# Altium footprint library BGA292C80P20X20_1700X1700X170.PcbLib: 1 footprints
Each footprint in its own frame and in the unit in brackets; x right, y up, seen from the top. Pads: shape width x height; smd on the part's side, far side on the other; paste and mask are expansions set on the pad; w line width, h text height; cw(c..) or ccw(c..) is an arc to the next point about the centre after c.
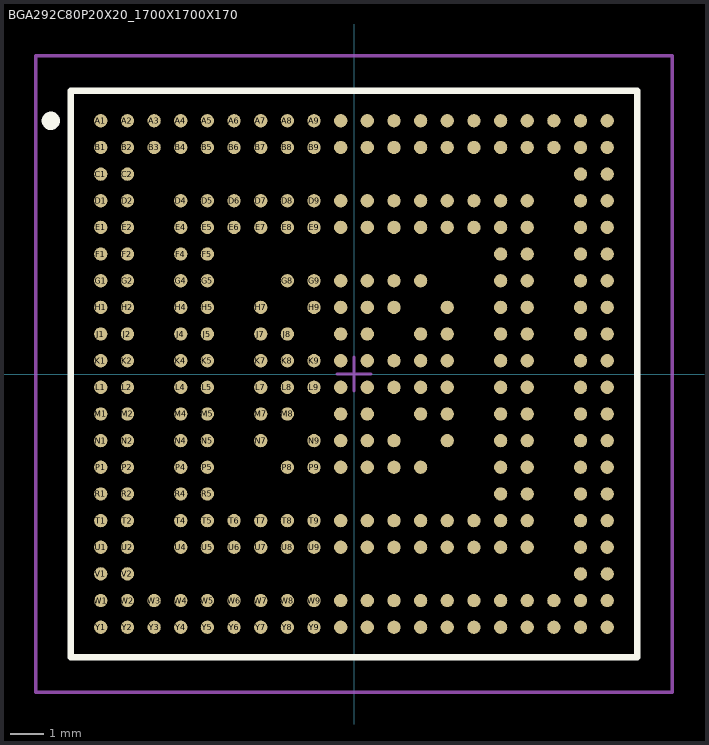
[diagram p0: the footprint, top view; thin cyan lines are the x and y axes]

## BGA292C80P20X20_1700X1700X170 [mm] "BGA,0.80mm pitch,square;292 pin,20 columns X 20 rows,17.00mm X 17.00mm X 1.70mm H"
height 1.7
pads (292):
  round 0.4 smd paste+0 mask+0: A1(-7.6,7.6) A2(-6.8,7.6) A3(-6,7.6) A4(-5.2,7.6) A5(-4.4,7.6) A6(-3.6,7.6) A7(-2.8,7.6) A8(-2,7.6) A9(-1.2,7.6) A10(-0.4,7.6) A11(0.4,7.6) A12(1.2,7.6) A13(2,7.6) A14(2.8,7.6) A15(3.6,7.6) A16(4.4,7.6) A17(5.2,7.6) A18(6,7.6) A19(6.8,7.6) A20(7.6,7.6) B1(-7.6,6.8) B2(-6.8,6.8) B3(-6,6.8) B4(-5.2,6.8) B5(-4.4,6.8) B6(-3.6,6.8) B7(-2.8,6.8) B8(-2,6.8) B9(-1.2,6.8) B10(-0.4,6.8) B11(0.4,6.8) B12(1.2,6.8) B13(2,6.8) B14(2.8,6.8) B15(3.6,6.8) B16(4.4,6.8) B17(5.2,6.8) B18(6,6.8) B19(6.8,6.8) B20(7.6,6.8) C1(-7.6,6) C2(-6.8,6) C19(6.8,6) C20(7.6,6) D1(-7.6,5.2) D2(-6.8,5.2) D4(-5.2,5.2) D5(-4.4,5.2) D6(-3.6,5.2) D7(-2.8,5.2) D8(-2,5.2) D9(-1.2,5.2) D10(-0.4,5.2) D11(0.4,5.2) D12(1.2,5.2) D13(2,5.2) D14(2.8,5.2) D15(3.6,5.2) D16(4.4,5.2) D17(5.2,5.2) D19(6.8,5.2) D20(7.6,5.2) E1(-7.6,4.4) E2(-6.8,4.4) E4(-5.2,4.4) E5(-4.4,4.4) E6(-3.6,4.4) E7(-2.8,4.4) E8(-2,4.4) E9(-1.2,4.4) E10(-0.4,4.4) E11(0.4,4.4) E12(1.2,4.4) E13(2,4.4) E14(2.8,4.4) E15(3.6,4.4) E16(4.4,4.4) E17(5.2,4.4) E19(6.8,4.4) E20(7.6,4.4) F1(-7.6,3.6) F2(-6.8,3.6) F4(-5.2,3.6) F5(-4.4,3.6) F16(4.4,3.6) F17(5.2,3.6) F19(6.8,3.6) F20(7.6,3.6) G1(-7.6,2.8) G2(-6.8,2.8) G4(-5.2,2.8) G5(-4.4,2.8) G8(-2,2.8) G9(-1.2,2.8) G10(-0.4,2.8) G11(0.4,2.8) G12(1.2,2.8) G13(2,2.8) G16(4.4,2.8) G17(5.2,2.8) G19(6.8,2.8) G20(7.6,2.8) H1(-7.6,2) H2(-6.8,2) H4(-5.2,2) H5(-4.4,2) H7(-2.8,2) H9(-1.2,2) H10(-0.4,2) H11(0.4,2) H12(1.2,2) H14(2.8,2) H16(4.4,2) H17(5.2,2) H19(6.8,2) H20(7.6,2) J1(-7.6,1.2) J2(-6.8,1.2) J4(-5.2,1.2) J5(-4.4,1.2) J7(-2.8,1.2) J8(-2,1.2) J10(-0.4,1.2) J11(0.4,1.2) J13(2,1.2) J14(2.8,1.2) J16(4.4,1.2) J17(5.2,1.2) J19(6.8,1.2) J20(7.6,1.2) K1(-7.6,0.4) K2(-6.8,0.4) K4(-5.2,0.4) K5(-4.4,0.4) K7(-2.8,0.4) K8(-2,0.4) K9(-1.2,0.4) K10(-0.4,0.4) K11(0.4,0.4) K12(1.2,0.4) K13(2,0.4) K14(2.8,0.4) K16(4.4,0.4) K17(5.2,0.4) K19(6.8,0.4) K20(7.6,0.4) L1(-7.6,-0.4) L2(-6.8,-0.4) L4(-5.2,-0.4) L5(-4.4,-0.4) L7(-2.8,-0.4) L8(-2,-0.4) L9(-1.2,-0.4) L10(-0.4,-0.4) L11(0.4,-0.4) L12(1.2,-0.4) L13(2,-0.4) L14(2.8,-0.4) L16(4.4,-0.4) L17(5.2,-0.4) L19(6.8,-0.4) L20(7.6,-0.4) M1(-7.6,-1.2) M2(-6.8,-1.2) M4(-5.2,-1.2) M5(-4.4,-1.2) M7(-2.8,-1.2) M8(-2,-1.2) M10(-0.4,-1.2) M11(0.4,-1.2) M13(2,-1.2) M14(2.8,-1.2) M16(4.4,-1.2) M17(5.2,-1.2) M19(6.8,-1.2) M20(7.6,-1.2) N1(-7.6,-2) N2(-6.8,-2) N4(-5.2,-2) N5(-4.4,-2) N7(-2.8,-2) N9(-1.2,-2) N10(-0.4,-2) N11(0.4,-2) N12(1.2,-2) N14(2.8,-2) N16(4.4,-2) N17(5.2,-2) N19(6.8,-2) N20(7.6,-2) P1(-7.6,-2.8) P2(-6.8,-2.8) P4(-5.2,-2.8) P5(-4.4,-2.8) P8(-2,-2.8) P9(-1.2,-2.8) P10(-0.4,-2.8) P11(0.4,-2.8) P12(1.2,-2.8) P13(2,-2.8) P16(4.4,-2.8) P17(5.2,-2.8) P19(6.8,-2.8) P20(7.6,-2.8) R1(-7.6,-3.6) R2(-6.8,-3.6) R4(-5.2,-3.6) R5(-4.4,-3.6) R16(4.4,-3.6) R17(5.2,-3.6) R19(6.8,-3.6) R20(7.6,-3.6) T1(-7.6,-4.4) T2(-6.8,-4.4) T4(-5.2,-4.4) T5(-4.4,-4.4) T6(-3.6,-4.4) T7(-2.8,-4.4) T8(-2,-4.4) T9(-1.2,-4.4) T10(-0.4,-4.4) T11(0.4,-4.4) T12(1.2,-4.4) T13(2,-4.4) T14(2.8,-4.4) T15(3.6,-4.4) T16(4.4,-4.4) T17(5.2,-4.4) T19(6.8,-4.4) T20(7.6,-4.4) U1(-7.6,-5.2) U2(-6.8,-5.2) U4(-5.2,-5.2) U5(-4.4,-5.2) U6(-3.6,-5.2) U7(-2.8,-5.2) U8(-2,-5.2) U9(-1.2,-5.2) U10(-0.4,-5.2) U11(0.4,-5.2) U12(1.2,-5.2) U13(2,-5.2) U14(2.8,-5.2) U15(3.6,-5.2) U16(4.4,-5.2) U17(5.2,-5.2) U19(6.8,-5.2) U20(7.6,-5.2) V1(-7.6,-6) V2(-6.8,-6) V19(6.8,-6) V20(7.6,-6) W1(-7.6,-6.8) W2(-6.8,-6.8) W3(-6,-6.8) W4(-5.2,-6.8) W5(-4.4,-6.8) W6(-3.6,-6.8) W7(-2.8,-6.8) W8(-2,-6.8) W9(-1.2,-6.8) W10(-0.4,-6.8) W11(0.4,-6.8) W12(1.2,-6.8) W13(2,-6.8) W14(2.8,-6.8) W15(3.6,-6.8) W16(4.4,-6.8) W17(5.2,-6.8) W18(6,-6.8) W19(6.8,-6.8) W20(7.6,-6.8) Y1(-7.6,-7.6) Y2(-6.8,-7.6) Y3(-6,-7.6) Y4(-5.2,-7.6) Y5(-4.4,-7.6) Y6(-3.6,-7.6) Y7(-2.8,-7.6) Y8(-2,-7.6) Y9(-1.2,-7.6) Y10(-0.4,-7.6) Y11(0.4,-7.6) Y12(1.2,-7.6) Y13(2,-7.6) Y14(2.8,-7.6) Y15(3.6,-7.6) Y16(4.4,-7.6) Y17(5.2,-7.6) Y18(6,-7.6) Y19(6.8,-7.6) Y20(7.6,-7.6)
Top Overlay:
  circle w0.3: c-9.1,7.6 r0.125
  lines w0.2: -8.5,-8.5 -8.5,8.5 8.5,8.5 8.5,-8.5 -8.5,-8.5
M3 (ASY_Text_Top):
  text ".DESIGNATOR" at 0,0 h1.2
M13 (CMP_Body_OTL_Top):
  lines w0.1: -8.5,-8.5 -8.5,8.5 8.5,8.5 8.5,-8.5 -8.5,-8.5
M15 (CMP_Courtyard_Top):
  lines w0.1: -0.5,0 0.5,0 ; 0,-0.5 0,0.5 ; -9.55,-9.55 -9.55,9.55 9.55,9.55 9.55,-9.55 -9.55,-9.55
3D body: height 0.45, standoff -0.05, extent -7.847,7.351 -7.35,7.849
3D body: height 1.71, standoff 1.7, extent -7.92,7.28 -7.32,7.879
3D body: height 0.45, standoff -0.05, extent -7.847,6.551 -7.35,7.049
3D body: height 0.45, standoff -0.05, extent -7.047,6.551 -6.55,7.049
3D body: height 0.45, standoff -0.05, extent -7.047,7.351 -6.55,7.849
3D body: height 0.45, standoff -0.05, extent -6.247,7.351 -5.75,7.849
3D body: height 0.45, standoff -0.05, extent -6.247,6.551 -5.75,7.049
3D body: height 0.45, standoff -0.05, extent -5.447,7.351 -4.95,7.849
3D body: height 0.45, standoff -0.05, extent -5.447,6.551 -4.95,7.049
3D body: height 0.45, standoff -0.05, extent -4.647,7.351 -4.15,7.849
3D body: height 0.45, standoff -0.05, extent -4.647,6.551 -4.15,7.049
3D body: height 0.45, standoff -0.05, extent -3.847,7.351 -3.35,7.849
3D body: height 0.45, standoff -0.05, extent -3.847,6.551 -3.35,7.049
3D body: height 0.45, standoff -0.05, extent -3.047,7.351 -2.55,7.849
3D body: height 0.45, standoff -0.05, extent -3.047,6.551 -2.55,7.049
3D body: height 0.45, standoff -0.05, extent -2.247,7.351 -1.75,7.849
3D body: height 0.45, standoff -0.05, extent -2.247,6.551 -1.75,7.049
3D body: height 0.45, standoff -0.05, extent -1.447,7.351 -0.95,7.849
3D body: height 0.45, standoff -0.05, extent -1.447,6.551 -0.95,7.049
3D body: height 0.45, standoff -0.05, extent -0.647,7.351 -0.15,7.849
3D body: height 0.45, standoff -0.05, extent -0.647,6.551 -0.15,7.049
3D body: height 0.45, standoff -0.05, extent 0.153,7.351 0.65,7.849
3D body: height 0.45, standoff -0.05, extent 0.153,6.551 0.65,7.049
3D body: height 0.45, standoff -0.05, extent 0.953,7.351 1.45,7.849
3D body: height 0.45, standoff -0.05, extent 0.953,6.551 1.45,7.049
3D body: height 0.45, standoff -0.05, extent 1.753,7.351 2.25,7.849
3D body: height 0.45, standoff -0.05, extent 1.753,6.551 2.25,7.049
3D body: height 0.45, standoff -0.05, extent 2.553,7.351 3.05,7.849
3D body: height 0.45, standoff -0.05, extent 2.553,6.551 3.05,7.049
3D body: height 0.45, standoff -0.05, extent 3.353,7.351 3.85,7.849
3D body: height 0.45, standoff -0.05, extent 3.353,6.551 3.85,7.049
3D body: height 0.45, standoff -0.05, extent 4.153,7.351 4.65,7.849
3D body: height 0.45, standoff -0.05, extent 4.153,6.551 4.65,7.049
3D body: height 0.45, standoff -0.05, extent 4.953,7.351 5.45,7.849
3D body: height 0.45, standoff -0.05, extent 4.953,6.551 5.45,7.049
3D body: height 0.45, standoff -0.05, extent 5.753,7.351 6.25,7.849
3D body: height 0.45, standoff -0.05, extent 5.753,6.551 6.25,7.049
3D body: height 0.45, standoff -0.05, extent 6.553,7.351 7.05,7.849
3D body: height 0.45, standoff -0.05, extent 6.553,6.551 7.05,7.049
3D body: height 0.45, standoff -0.05, extent 7.353,7.351 7.85,7.849
3D body: height 0.45, standoff -0.05, extent 7.353,6.551 7.85,7.049
3D body: height 0.45, standoff -0.05, extent 6.553,5.751 7.05,6.249
3D body: height 0.45, standoff -0.05, extent 6.553,4.951 7.05,5.449
3D body: height 0.45, standoff -0.05, extent 6.553,4.151 7.05,4.649
3D body: height 0.45, standoff -0.05, extent 6.553,3.351 7.05,3.849
3D body: height 0.45, standoff -0.05, extent 6.553,2.551 7.05,3.049
3D body: height 0.45, standoff -0.05, extent 6.553,1.751 7.05,2.249
3D body: height 0.45, standoff -0.05, extent 6.553,0.951 7.05,1.449
3D body: height 0.45, standoff -0.05, extent 6.553,0.151 7.05,0.649
3D body: height 0.45, standoff -0.05, extent 6.553,-0.649 7.05,-0.151
3D body: height 0.45, standoff -0.05, extent 6.553,-1.449 7.05,-0.951
3D body: height 0.45, standoff -0.05, extent 6.553,-2.249 7.05,-1.751
3D body: height 0.45, standoff -0.05, extent 6.553,-3.049 7.05,-2.551
3D body: height 0.45, standoff -0.05, extent 6.553,-3.849 7.05,-3.351
3D body: height 0.45, standoff -0.05, extent 6.553,-4.649 7.05,-4.151
3D body: height 0.45, standoff -0.05, extent 6.553,-5.449 7.05,-4.951
3D body: height 0.45, standoff -0.05, extent 6.553,-6.249 7.05,-5.751
3D body: height 0.45, standoff -0.05, extent 6.553,-7.049 7.05,-6.551
3D body: height 0.45, standoff -0.05, extent 6.553,-7.849 7.05,-7.351
3D body: height 0.45, standoff -0.05, extent 7.353,-7.849 7.85,-7.351
3D body: height 0.45, standoff -0.05, extent 7.353,-7.049 7.85,-6.551
3D body: height 0.45, standoff -0.05, extent 7.353,-6.249 7.85,-5.751
3D body: height 0.45, standoff -0.05, extent 7.353,-5.449 7.85,-4.951
3D body: height 0.45, standoff -0.05, extent 7.353,-4.649 7.85,-4.151
3D body: height 0.45, standoff -0.05, extent 7.353,-3.849 7.85,-3.351
3D body: height 0.45, standoff -0.05, extent 7.353,-3.049 7.85,-2.551
3D body: height 0.45, standoff -0.05, extent 7.353,-2.249 7.85,-1.751
3D body: height 0.45, standoff -0.05, extent 7.353,-1.449 7.85,-0.951
3D body: height 0.45, standoff -0.05, extent 7.353,-0.649 7.85,-0.151
3D body: height 0.45, standoff -0.05, extent 7.353,0.151 7.85,0.649
3D body: height 0.45, standoff -0.05, extent 7.353,0.951 7.85,1.449
3D body: height 0.45, standoff -0.05, extent 7.353,1.751 7.85,2.249
3D body: height 0.45, standoff -0.05, extent 7.353,2.551 7.85,3.049
3D body: height 0.45, standoff -0.05, extent 7.353,3.351 7.85,3.849
3D body: height 0.45, standoff -0.05, extent 7.353,4.151 7.85,4.649
3D body: height 0.45, standoff -0.05, extent 7.353,4.951 7.85,5.449
3D body: height 0.45, standoff -0.05, extent 7.353,5.751 7.85,6.249
3D body: height 0.45, standoff -0.05, extent -7.847,-7.049 -7.35,-6.551
3D body: height 0.45, standoff -0.05, extent -7.847,-7.849 -7.35,-7.351
3D body: height 0.45, standoff -0.05, extent -7.047,-7.049 -6.55,-6.551
3D body: height 0.45, standoff -0.05, extent -7.047,-7.849 -6.55,-7.351
3D body: height 0.45, standoff -0.05, extent -6.247,-7.049 -5.75,-6.551
3D body: height 0.45, standoff -0.05, extent -6.247,-7.849 -5.75,-7.351
3D body: height 0.45, standoff -0.05, extent -5.447,-7.049 -4.95,-6.551
3D body: height 0.45, standoff -0.05, extent -5.447,-7.849 -4.95,-7.351
3D body: height 0.45, standoff -0.05, extent -4.647,-7.049 -4.15,-6.551
3D body: height 0.45, standoff -0.05, extent -4.647,-7.849 -4.15,-7.351
3D body: height 0.45, standoff -0.05, extent -3.847,-7.049 -3.35,-6.551
3D body: height 0.45, standoff -0.05, extent -3.847,-7.849 -3.35,-7.351
3D body: height 0.45, standoff -0.05, extent -3.047,-7.049 -2.55,-6.551
3D body: height 0.45, standoff -0.05, extent -3.047,-7.849 -2.55,-7.351
3D body: height 0.45, standoff -0.05, extent -2.247,-7.049 -1.75,-6.551
3D body: height 0.45, standoff -0.05, extent -2.247,-7.849 -1.75,-7.351
3D body: height 0.45, standoff -0.05, extent -1.447,-7.049 -0.95,-6.551
3D body: height 0.45, standoff -0.05, extent -1.447,-7.849 -0.95,-7.351
3D body: height 0.45, standoff -0.05, extent -0.647,-7.049 -0.15,-6.551
3D body: height 0.45, standoff -0.05, extent -0.647,-7.849 -0.15,-7.351
3D body: height 0.45, standoff -0.05, extent 0.153,-7.049 0.65,-6.551
3D body: height 0.45, standoff -0.05, extent 0.153,-7.849 0.65,-7.351
3D body: height 0.45, standoff -0.05, extent 0.953,-7.049 1.45,-6.551
3D body: height 0.45, standoff -0.05, extent 0.953,-7.849 1.45,-7.351
3D body: height 0.45, standoff -0.05, extent 1.753,-7.049 2.25,-6.551
3D body: height 0.45, standoff -0.05, extent 1.753,-7.849 2.25,-7.351
3D body: height 0.45, standoff -0.05, extent 2.553,-7.049 3.05,-6.551
3D body: height 0.45, standoff -0.05, extent 2.553,-7.849 3.05,-7.351
3D body: height 0.45, standoff -0.05, extent 3.353,-7.049 3.85,-6.551
3D body: height 0.45, standoff -0.05, extent 3.353,-7.849 3.85,-7.351
3D body: height 0.45, standoff -0.05, extent 4.153,-7.049 4.65,-6.551
3D body: height 0.45, standoff -0.05, extent 4.153,-7.849 4.65,-7.351
3D body: height 0.45, standoff -0.05, extent 4.953,-7.049 5.45,-6.551
3D body: height 0.45, standoff -0.05, extent 4.953,-7.849 5.45,-7.351
3D body: height 0.45, standoff -0.05, extent 5.753,-7.049 6.25,-6.551
3D body: height 0.45, standoff -0.05, extent 5.753,-7.849 6.25,-7.351
3D body: height 0.45, standoff -0.05, extent -7.847,5.751 -7.35,6.249
3D body: height 0.45, standoff -0.05, extent -7.847,4.951 -7.35,5.449
3D body: height 0.45, standoff -0.05, extent -7.847,4.151 -7.35,4.649
3D body: height 0.45, standoff -0.05, extent -7.847,3.351 -7.35,3.849
3D body: height 0.45, standoff -0.05, extent -7.847,2.551 -7.35,3.049
3D body: height 0.45, standoff -0.05, extent -7.847,1.751 -7.35,2.249
3D body: height 0.45, standoff -0.05, extent -7.847,0.951 -7.35,1.449
3D body: height 0.45, standoff -0.05, extent -7.847,0.151 -7.35,0.649
3D body: height 0.45, standoff -0.05, extent -7.847,-0.649 -7.35,-0.151
3D body: height 0.45, standoff -0.05, extent -7.847,-1.449 -7.35,-0.951
3D body: height 0.45, standoff -0.05, extent -7.847,-2.249 -7.35,-1.751
3D body: height 0.45, standoff -0.05, extent -7.847,-3.049 -7.35,-2.551
3D body: height 0.45, standoff -0.05, extent -7.847,-3.849 -7.35,-3.351
3D body: height 0.45, standoff -0.05, extent -7.847,-4.649 -7.35,-4.151
3D body: height 0.45, standoff -0.05, extent -7.847,-5.449 -7.35,-4.951
3D body: height 0.45, standoff -0.05, extent -7.047,-5.449 -6.55,-4.951
3D body: height 0.45, standoff -0.05, extent -7.047,-4.649 -6.55,-4.151
3D body: height 0.45, standoff -0.05, extent -7.047,-3.849 -6.55,-3.351
3D body: height 0.45, standoff -0.05, extent -7.047,-3.049 -6.55,-2.551
3D body: height 0.45, standoff -0.05, extent -7.047,-2.249 -6.55,-1.751
3D body: height 0.45, standoff -0.05, extent -7.047,-1.449 -6.55,-0.951
3D body: height 0.45, standoff -0.05, extent -7.047,-0.649 -6.55,-0.151
3D body: height 0.45, standoff -0.05, extent -7.047,0.151 -6.55,0.649
3D body: height 0.45, standoff -0.05, extent -7.047,0.951 -6.55,1.449
3D body: height 0.45, standoff -0.05, extent -7.047,1.751 -6.55,2.249
3D body: height 0.45, standoff -0.05, extent -7.047,2.551 -6.55,3.049
3D body: height 0.45, standoff -0.05, extent -7.047,3.351 -6.55,3.849
3D body: height 0.45, standoff -0.05, extent -7.047,4.151 -6.55,4.649
3D body: height 0.45, standoff -0.05, extent -7.047,4.951 -6.55,5.449
3D body: height 0.45, standoff -0.05, extent -7.047,5.751 -6.55,6.249
3D body: height 0.45, standoff -0.05, extent -5.447,4.951 -4.95,5.449
3D body: height 0.45, standoff -0.05, extent -5.447,4.151 -4.95,4.649
3D body: height 0.45, standoff -0.05, extent -5.447,3.351 -4.95,3.849
3D body: height 0.45, standoff -0.05, extent -5.447,2.551 -4.95,3.049
3D body: height 0.45, standoff -0.05, extent -5.447,1.751 -4.95,2.249
3D body: height 0.45, standoff -0.05, extent -5.447,0.951 -4.95,1.449
3D body: height 0.45, standoff -0.05, extent -5.447,0.151 -4.95,0.649
3D body: height 0.45, standoff -0.05, extent -5.447,-0.649 -4.95,-0.151
3D body: height 0.45, standoff -0.05, extent -5.447,-1.449 -4.95,-0.951
3D body: height 0.45, standoff -0.05, extent -5.447,-2.249 -4.95,-1.751
3D body: height 0.45, standoff -0.05, extent -5.447,-3.049 -4.95,-2.551
3D body: height 0.45, standoff -0.05, extent -5.447,-3.849 -4.95,-3.351
3D body: height 0.45, standoff -0.05, extent -5.447,-4.649 -4.95,-4.151
3D body: height 0.45, standoff -0.05, extent -5.447,-5.449 -4.95,-4.951
3D body: height 0.45, standoff -0.05, extent -4.647,-5.449 -4.15,-4.951
3D body: height 0.45, standoff -0.05, extent -4.647,-4.649 -4.15,-4.151
3D body: height 0.45, standoff -0.05, extent -4.647,-3.849 -4.15,-3.351
3D body: height 0.45, standoff -0.05, extent -4.647,-3.049 -4.15,-2.551
3D body: height 0.45, standoff -0.05, extent -4.647,-2.249 -4.15,-1.751
3D body: height 0.45, standoff -0.05, extent -4.647,-1.449 -4.15,-0.951
3D body: height 0.45, standoff -0.05, extent -4.647,-0.649 -4.15,-0.151
3D body: height 0.45, standoff -0.05, extent -4.647,0.151 -4.15,0.649
3D body: height 0.45, standoff -0.05, extent -4.647,0.951 -4.15,1.449
3D body: height 0.45, standoff -0.05, extent -4.647,1.751 -4.15,2.249
3D body: height 0.45, standoff -0.05, extent -4.647,2.551 -4.15,3.049
3D body: height 0.45, standoff -0.05, extent -4.647,3.351 -4.15,3.849
3D body: height 0.45, standoff -0.05, extent -4.647,4.151 -4.15,4.649
3D body: height 0.45, standoff -0.05, extent -4.647,4.951 -4.15,5.449
3D body: height 0.45, standoff -0.05, extent 4.153,4.951 4.65,5.449
3D body: height 0.45, standoff -0.05, extent 4.153,4.149 4.65,4.647
3D body: height 0.45, standoff -0.05, extent 4.153,3.351 4.65,3.849
3D body: height 0.45, standoff -0.05, extent 4.153,2.551 4.65,3.049
3D body: height 0.45, standoff -0.05, extent 4.153,1.751 4.65,2.249
3D body: height 0.45, standoff -0.05, extent 4.153,0.951 4.65,1.449
3D body: height 0.45, standoff -0.05, extent 4.153,0.151 4.65,0.649
3D body: height 0.45, standoff -0.05, extent 4.153,-0.649 4.65,-0.151
3D body: height 0.45, standoff -0.05, extent 4.153,-1.449 4.65,-0.951
3D body: height 0.45, standoff -0.05, extent 4.153,-2.249 4.65,-1.751
3D body: height 0.45, standoff -0.05, extent 4.153,-3.049 4.65,-2.551
3D body: height 0.45, standoff -0.05, extent 4.153,-3.849 4.65,-3.351
3D body: height 0.45, standoff -0.05, extent 4.153,-4.649 4.65,-4.151
3D body: height 0.45, standoff -0.05, extent 4.153,-5.449 4.65,-4.951
3D body: height 0.45, standoff -0.05, extent 4.953,-5.449 5.45,-4.951
3D body: height 0.45, standoff -0.05, extent 4.953,-4.649 5.45,-4.151
3D body: height 0.45, standoff -0.05, extent 4.953,-3.849 5.45,-3.351
3D body: height 0.45, standoff -0.05, extent 4.953,-3.049 5.45,-2.551
3D body: height 0.45, standoff -0.05, extent 4.953,-2.249 5.45,-1.751
3D body: height 0.45, standoff -0.05, extent 4.953,-1.449 5.45,-0.951
3D body: height 0.45, standoff -0.05, extent 4.953,-0.649 5.45,-0.151
3D body: height 0.45, standoff -0.05, extent 4.953,0.151 5.45,0.649
3D body: height 0.45, standoff -0.05, extent 4.953,0.951 5.45,1.449
3D body: height 0.45, standoff -0.05, extent 4.953,1.751 5.45,2.249
3D body: height 0.45, standoff -0.05, extent 4.953,2.551 5.45,3.049
3D body: height 0.45, standoff -0.05, extent 4.953,3.351 5.45,3.849
3D body: height 0.45, standoff -0.05, extent 4.953,4.151 5.45,4.649
3D body: height 0.45, standoff -0.05, extent 4.953,4.951 5.45,5.449
3D body: height 0.45, standoff -0.05, extent -3.847,4.951 -3.35,5.449
3D body: height 0.45, standoff -0.05, extent -3.847,4.151 -3.35,4.649
3D body: height 0.45, standoff -0.05, extent -3.847,-4.649 -3.35,-4.151
3D body: height 0.45, standoff -0.05, extent -3.847,-5.449 -3.35,-4.951
3D body: height 0.45, standoff -0.05, extent -3.047,-5.449 -2.55,-4.951
3D body: height 0.45, standoff -0.05, extent -3.047,-4.649 -2.55,-4.151
3D body: height 0.45, standoff -0.05, extent -3.047,-2.249 -2.55,-1.751
3D body: height 0.45, standoff -0.05, extent -3.047,-1.449 -2.55,-0.951
3D body: height 0.45, standoff -0.05, extent -3.047,-0.649 -2.55,-0.151
3D body: height 0.45, standoff -0.05, extent -3.047,0.151 -2.55,0.649
3D body: height 0.45, standoff -0.05, extent -3.047,0.951 -2.55,1.449
3D body: height 0.45, standoff -0.05, extent -3.047,1.751 -2.55,2.249
3D body: height 0.45, standoff -0.05, extent -3.047,4.151 -2.55,4.649
3D body: height 0.45, standoff -0.05, extent -3.047,4.951 -2.55,5.449
3D body: height 0.45, standoff -0.05, extent -2.247,4.951 -1.75,5.449
3D body: height 0.45, standoff -0.05, extent -2.247,4.151 -1.75,4.649
3D body: height 0.45, standoff -0.05, extent -2.267,2.531 -1.77,3.029
3D body: height 0.45, standoff -0.05, extent -2.247,0.951 -1.75,1.449
3D body: height 0.45, standoff -0.05, extent -2.247,0.151 -1.75,0.649
3D body: height 0.45, standoff -0.05, extent -2.247,-0.649 -1.75,-0.151
3D body: height 0.45, standoff -0.05, extent -2.247,-1.449 -1.75,-0.951
3D body: height 0.45, standoff -0.05, extent -2.247,-3.049 -1.75,-2.551
3D body: height 0.45, standoff -0.05, extent -2.247,-4.649 -1.75,-4.151
3D body: height 0.45, standoff -0.05, extent -2.247,-5.449 -1.75,-4.951
3D body: height 0.45, standoff -0.05, extent -1.447,4.951 -0.95,5.449
3D body: height 0.45, standoff -0.05, extent -1.447,4.151 -0.95,4.649
3D body: height 0.45, standoff -0.05, extent -1.467,2.531 -0.97,3.029
3D body: height 0.45, standoff -0.05, extent -1.447,1.751 -0.95,2.249
3D body: height 0.45, standoff -0.05, extent -1.447,0.151 -0.95,0.649
3D body: height 0.45, standoff -0.05, extent -1.447,-0.649 -0.95,-0.151
3D body: height 0.45, standoff -0.05, extent -1.447,-2.249 -0.95,-1.751
3D body: height 0.45, standoff -0.05, extent -1.447,-3.049 -0.95,-2.551
3D body: height 0.45, standoff -0.05, extent -1.447,-4.649 -0.95,-4.151
3D body: height 0.45, standoff -0.05, extent -1.447,-5.449 -0.95,-4.951
3D body: height 0.45, standoff -0.05, extent -0.647,4.951 -0.15,5.449
3D body: height 0.45, standoff -0.05, extent -0.647,4.151 -0.15,4.649
3D body: height 0.45, standoff -0.05, extent -0.667,2.531 -0.17,3.029
3D body: height 0.45, standoff -0.05, extent -0.647,1.751 -0.15,2.249
3D body: height 0.45, standoff -0.05, extent -0.647,0.951 -0.15,1.449
3D body: height 0.45, standoff -0.05, extent -0.647,0.151 -0.15,0.649
3D body: height 0.45, standoff -0.05, extent -0.647,-0.649 -0.15,-0.151
3D body: height 0.45, standoff -0.05, extent -0.647,-1.449 -0.15,-0.951
3D body: height 0.45, standoff -0.05, extent -0.647,-2.249 -0.15,-1.751
3D body: height 0.45, standoff -0.05, extent -0.647,-3.049 -0.15,-2.551
3D body: height 0.45, standoff -0.05, extent -0.647,-4.649 -0.15,-4.151
3D body: height 0.45, standoff -0.05, extent -0.647,-5.449 -0.15,-4.951
3D body: height 0.45, standoff -0.05, extent 0.153,4.951 0.65,5.449
3D body: height 0.45, standoff -0.05, extent 0.153,4.151 0.65,4.649
3D body: height 0.45, standoff -0.05, extent 0.133,2.531 0.63,3.029
3D body: height 0.45, standoff -0.05, extent 0.153,1.751 0.65,2.249
3D body: height 0.45, standoff -0.05, extent 0.153,0.951 0.65,1.449
3D body: height 0.45, standoff -0.05, extent 0.153,0.151 0.65,0.649
3D body: height 0.45, standoff -0.05, extent 0.153,-0.649 0.65,-0.151
3D body: height 0.45, standoff -0.05, extent 0.153,-1.449 0.65,-0.951
3D body: height 0.45, standoff -0.05, extent 0.153,-2.249 0.65,-1.751
3D body: height 0.45, standoff -0.05, extent 0.153,-3.049 0.65,-2.551
3D body: height 0.45, standoff -0.05, extent 0.153,-4.649 0.65,-4.151
3D body: height 0.45, standoff -0.05, extent 0.153,-5.449 0.65,-4.951
3D body: height 0.45, standoff -0.05, extent 0.953,4.951 1.45,5.449
3D body: height 0.45, standoff -0.05, extent 0.953,4.151 1.45,4.649
3D body: height 0.45, standoff -0.05, extent 0.933,2.531 1.43,3.029
3D body: height 0.45, standoff -0.05, extent 0.953,1.751 1.45,2.249
3D body: height 0.45, standoff -0.05, extent 0.953,0.151 1.45,0.649
3D body: height 0.45, standoff -0.05, extent 0.953,-0.649 1.45,-0.151
3D body: height 0.45, standoff -0.05, extent 0.953,-2.249 1.45,-1.751
3D body: height 0.45, standoff -0.05, extent 0.953,-3.049 1.45,-2.551
3D body: height 0.45, standoff -0.05, extent 0.953,-4.649 1.45,-4.151
3D body: height 0.45, standoff -0.05, extent 0.953,-5.449 1.45,-4.951
3D body: height 0.45, standoff -0.05, extent 1.753,4.951 2.25,5.449
3D body: height 0.45, standoff -0.05, extent 1.753,4.151 2.25,4.649
3D body: height 0.45, standoff -0.05, extent 1.733,2.531 2.23,3.029
3D body: height 0.45, standoff -0.05, extent 1.753,0.951 2.25,1.449
3D body: height 0.45, standoff -0.05, extent 1.753,0.151 2.25,0.649
3D body: height 0.45, standoff -0.05, extent 1.753,-0.649 2.25,-0.151
3D body: height 0.45, standoff -0.05, extent 1.753,-1.449 2.25,-0.951
3D body: height 0.45, standoff -0.05, extent 1.753,-3.049 2.25,-2.551
3D body: height 0.45, standoff -0.05, extent 1.753,-4.649 2.25,-4.151
3D body: height 0.45, standoff -0.05, extent 1.753,-5.449 2.25,-4.951
3D body: height 0.45, standoff -0.05, extent 2.553,4.951 3.05,5.449
3D body: height 0.45, standoff -0.05, extent 2.553,4.151 3.05,4.649
3D body: height 0.45, standoff -0.05, extent 2.553,1.751 3.05,2.249
3D body: height 0.45, standoff -0.05, extent 2.553,0.951 3.05,1.449
3D body: height 0.45, standoff -0.05, extent 2.553,0.151 3.05,0.649
3D body: height 0.45, standoff -0.05, extent 2.553,-0.649 3.05,-0.151
3D body: height 0.45, standoff -0.05, extent 2.553,-1.449 3.05,-0.951
3D body: height 0.45, standoff -0.05, extent 2.553,-2.249 3.05,-1.751
3D body: height 0.45, standoff -0.05, extent 2.553,-4.649 3.05,-4.151
3D body: height 0.45, standoff -0.05, extent 2.553,-5.449 3.05,-4.951
3D body: height 0.45, standoff -0.05, extent 3.353,4.951 3.85,5.449
3D body: height 0.45, standoff -0.05, extent 3.353,4.151 3.85,4.649
3D body: height 0.45, standoff -0.05, extent 3.353,-4.649 3.85,-4.151
3D body: height 0.45, standoff -0.05, extent 3.353,-5.449 3.85,-4.951
3D body: height 0.45, standoff -0.05, extent -7.047,-6.249 -6.55,-5.751
3D body: height 0.45, standoff -0.05, extent -7.847,-6.249 -7.35,-5.751
3D body: height 1.7, standoff 0.33, extent -8.52,-8.52 8.479,8.479
3D body: height 1.71, standoff 1.7, extent 4.571,4.676 5.513,5.478
3D body: height 1.71, standoff 1.7, extent 5.68,4.98 6.28,5.579
3D body: height 1.71, standoff 1.7, extent 4.261,4.056 6.122,6.258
